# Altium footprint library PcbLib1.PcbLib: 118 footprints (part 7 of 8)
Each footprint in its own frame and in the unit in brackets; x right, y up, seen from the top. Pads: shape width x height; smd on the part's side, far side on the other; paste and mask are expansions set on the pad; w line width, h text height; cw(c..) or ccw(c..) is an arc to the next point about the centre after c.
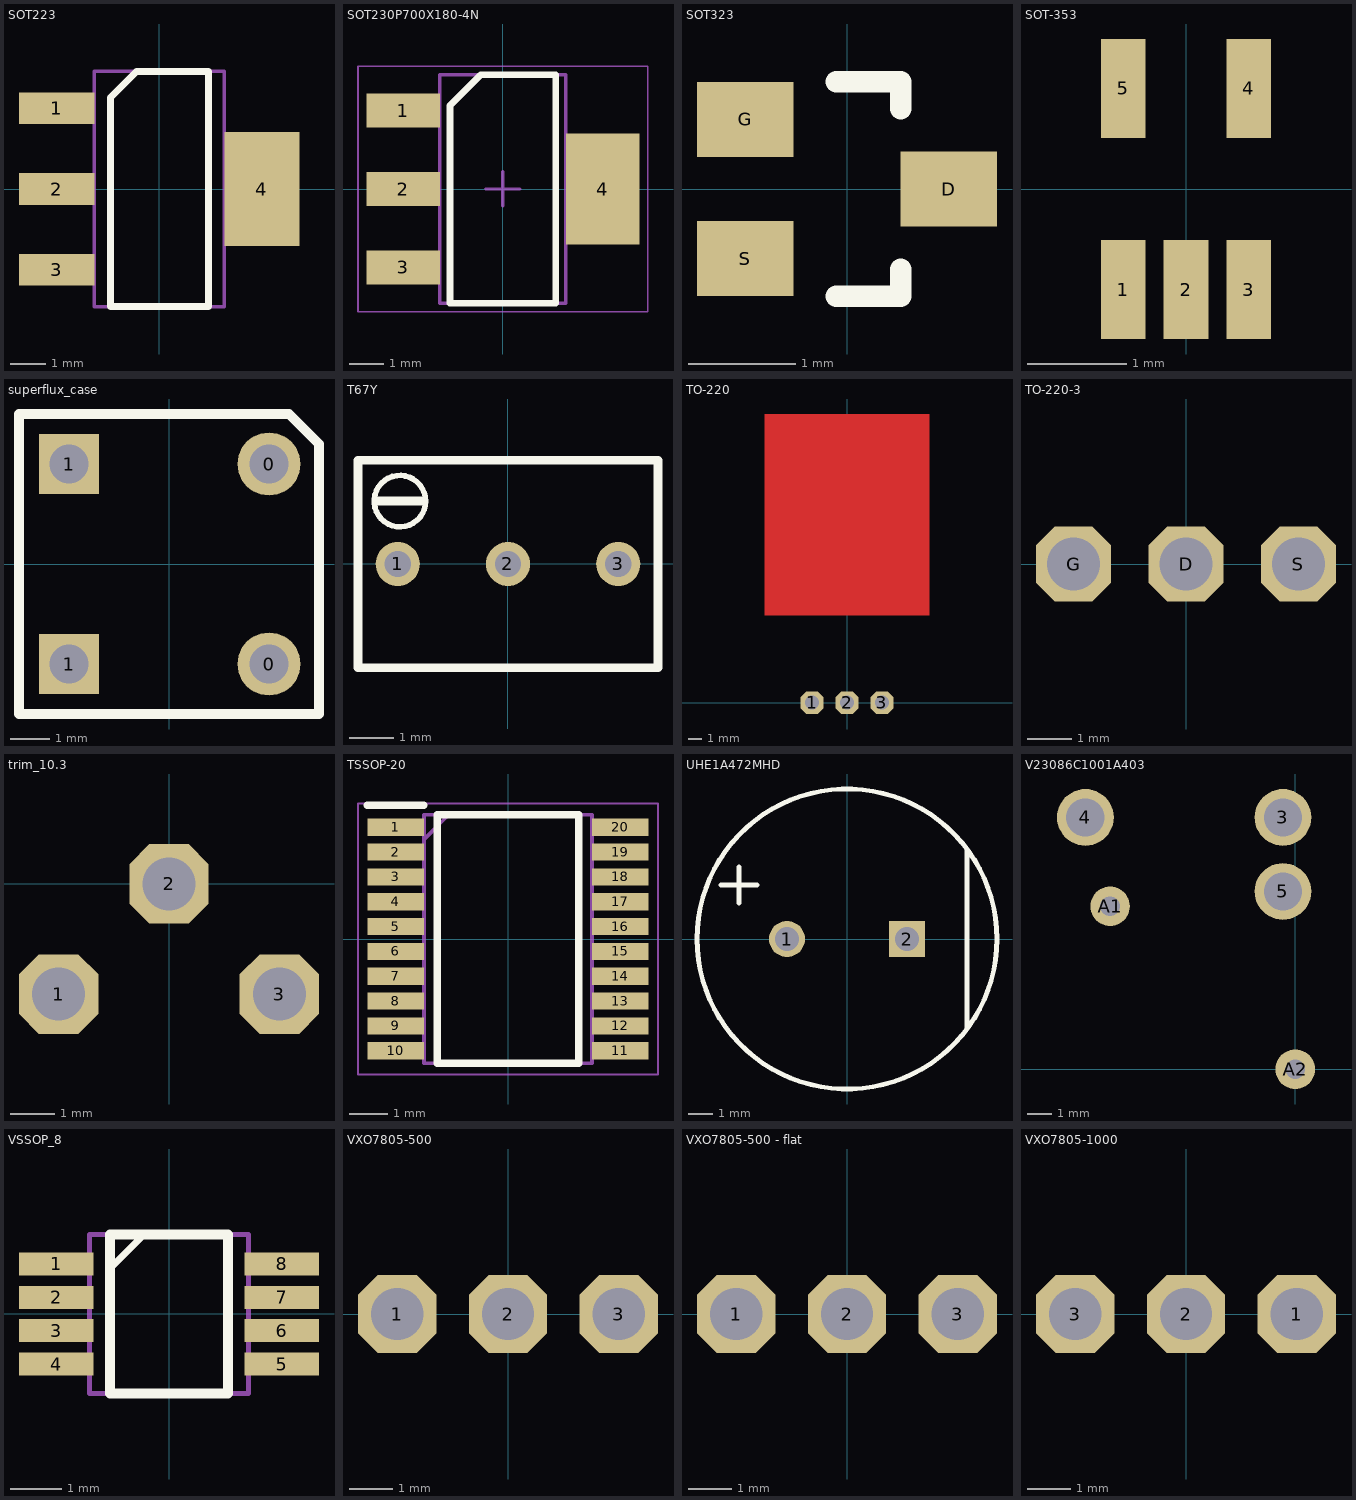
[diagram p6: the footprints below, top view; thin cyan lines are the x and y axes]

## SOT223 [mm]
height 1.8
pads (4):
  rect 2.15x0.9 smd: 1(-2.925,2.3) 2(-2.925,0) 3(-2.925,-2.3)
  rect 2.15x3.25 smd: 4(2.925,0)
Top Overlay:
  lines w0.2: -1.397,-3.35 1.397,-3.35 1.397,3.35 -0.65,3.35 -1.397,2.603 -1.397,-3.35
Mechanical 13:
  lines w0.1: -1.85,-3.35 1.85,-3.35 1.85,3.35 -1.85,3.35 -1.85,-3.35
3D body "SOT223.step": height 1.8, standoff 0, extent -3.5,-3.35 3.5,3.35

## SOT230P700X180-4N [mm] "SOT223, 4-Leads, Body 6,50x7,00mm (avg), Pitch 2,30mm, IPC Medium Density"
height 1.8
pads (4):
  rect 2.15x1 smd: 1(-2.925,2.3) 2(-2.925,0) 3(-2.925,-2.3)
  rect 2.15x3.25 smd: 4(2.925,0)
Top Overlay:
  lines w0.2: -1.55,-3.35 -1.55,2.45 -0.65,3.35 1.55,3.35 1.55,-3.35 -1.55,-3.35
Mechanical 13:
  lines w0.1: -1.85,-3.35 -1.85,3.35 1.85,3.35 1.85,-3.35 -1.85,-3.35
Mechanical 15:
  lines w0.05: -4.25,-3.6 -4.25,3.6 4.25,3.6 4.25,-3.6 -4.25,-3.6
  lines w0.1: -0.5,0 0.5,0 ; 0,-0.5 0,0.5
3D body "SOT-223.step": height 1.81, standoff 0, extent -3.645,-3.353 3.645,3.353

## SOT323 [mm] "SOT23, 3-Leads, Body 1,90x2,10mm, Pitch 0,65mm, IPC Medium Density"
height 1.1
pads (3):
  rect 0.9x0.7 smd: D(0.95,0) G(-0.95,0.65) S(-0.95,-0.65)
Top Overlay:
  lines w0.2: -0.1,-1 0.5,-1 0.5,-0.75 ; -0.1,1 0.5,1 0.5,0.75
3D body "SOT323.step": height 1.1, standoff 0, extent -1.1,-1 1.1,1

## SOT-353 [mm]
pads (5):
  rect 0.45x1 smd: 1(-0.635,-1.016) 2(0,-1.016) 3(0.635,-1.016) 4(0.635,1.016) 5(-0.635,1.016)
3D body "sot353.step": height 1, standoff 0, extent -1.05,-1.15 1.05,1.15

## superflux_case [mm]
pads (4):
  round 1.6 hole 1: 0(2.54,-2.54) 0(2.54,2.54)
  rect 1.524x1.524 hole 1: 1(-2.54,-2.54) 1(-2.54,2.54)
Top Overlay:
  lines w0.254: 2.99,3.81 -3.81,3.81 -3.81,-3.81 3.81,-3.81 3.81,3.048 3.048,3.81

## T67Y [mm] "SR Passives potentiometer"
pads (3):
  round 1 hole 0.6: 1(-2.5,0) 2(0,0) 3(2.5,0)
Top Overlay:
  circle w0.127: c-2.45,1.425 r0.583
  lines w0.2: -2.95,1.425 -1.95,1.425 ; -3.4,-2.35 3.4,-2.35 3.4,2.35 -3.4,2.35 -3.4,-2.35
3D body "T93YA.STEP": height 11.1, standoff -3, extent -4.85,-2.5 4.85,2.5

## TO-220 [mm]
pads (3):
  oct 1.65x1.65 hole 1: 1(-2.54,0) 2(0,0) 3(2.54,0)
Top Layer:
  region: -5.969,20.955 5.969,20.955 5.969,6.35 -5.969,6.35
3D body "TO-220_horizontal.step": height 4.55, standoff -7.08, extent -4.95,-0.247 4.95,19.966

## TO-220-3 [mm]
pads (3):
  oct 1.7x1.7 hole 1.2 mask+0.05: D(0,0) G(-2.54,0) S(2.54,0)
3D body "TO-220-3.STEP": height 19.76, standoff -2.2, extent -4.95,-2.1 4.95,2.4

## trim_10.3 [mm] "10.3x4.5mm body vertical"
pads (3):
  oct 1.8x1.8 hole 1.2: 1(-2.5,-2.5) 2(0,0) 3(2.5,-2.5)
3D body "User Library-PT10LH.step": height 12.1, standoff -3.5, extent -5.15,-2.76 5.15,2

## TSSOP-20 [mm]
pads (20):
  rect 1.475x0.45 smd: 1(-2.938,2.925) 2(-2.938,2.275) 3(-2.938,1.625) 4(-2.938,0.975) 5(-2.938,0.325) 6(-2.938,-0.325) 7(-2.938,-0.975) 8(-2.938,-1.625) 9(-2.938,-2.275) 10(-2.938,-2.925) 11(2.938,-2.925) 12(2.938,-2.275) 13(2.938,-1.625) 14(2.938,-0.975) 15(2.938,-0.325) 16(2.938,0.325) 17(2.938,0.975) 18(2.938,1.625) 19(2.938,2.275) 20(2.938,2.925)
Top Overlay:
  lines w0.2: -3.675,3.5 -2.2,3.5 ; -1.85,-3.25 1.85,-3.25 1.85,3.25 -1.85,3.25 -1.85,-3.25
Mechanical 15:
  lines w0.1: -2.2,2.6 -1.55,3.25 ; -2.2,-3.25 2.2,-3.25 2.2,3.25 -2.2,3.25 -2.2,-3.25
Mechanical 20:
  lines w0.05: -3.925,-3.55 3.925,-3.55 3.925,3.55 -3.925,3.55 -3.925,-3.55
3D body "TXB0108PWR.stp": height 1.2, standoff 0, extent -3.2,-3.25 3.2,3.25

## UHE1A472MHD [mm] "12.5x35.5 ALU ELKO"
pads (2):
  round 1.5 hole 1: 1(-2.5,0)
  rect 1.5x1.5 hole 1: 2(2.5,0)
Top Overlay:
  circle w0.2: c0,0 r6.25
  lines w0.2: -5.25,2.25 -3.75,2.25 ; -4.5,1.5 -4.5,3 ; 5,-3.75 5,3.75
3D body "12.5x35.5_radial.STEP": height 35.5, standoff -3, extent -6.25,-6.248 6.25,6.25

## V23086C1001A403 [mm]
pads (5):
  round 2.3 hole 1.55: 3(-0.5,10.2) 4(-8.5,10.2) 5(-0.5,7.2)
  round 1.6 hole 0.8: A1(-7.5,6.6) A2(0,0)
3D body "c-1393280-6-b1-3d.STEP": height 10, standoff -2.7, extent -10.191,-1.397 1.809,11.603

## VSSOP_8 [mm]
height 1.1
pads (8):
  rect 1.45x0.45 smd: 1(-2.2,0.975) 2(-2.2,0.325) 3(-2.2,-0.325) 4(-2.2,-0.975) 5(2.2,-0.975) 6(2.2,-0.325) 7(2.2,0.325) 8(2.2,0.975)
Top Overlay:
  lines w0.127: -1.15,0.889 -0.508,1.531
  lines w0.2: -1.15,-1.55 -1.15,1.55 1.15,1.55 1.15,-1.55 -1.15,-1.55
Mechanical 13:
  lines w0.1: -1.55,-1.55 -1.55,1.55 1.55,1.55 1.55,-1.55 -1.55,-1.55
3D body "VSSOP_8.step": height 1.1, standoff 0, extent -2.45,-1.55 2.45,1.55

## VXO7805-500 [mm]
pads (3):
  oct 1.8x1.8 hole 1.2: 1(-2.54,0) 2(0,0) 3(2.54,0)
3D body "CUI_VXO7805-500.step": height 11.25, standoff -3.85, extent -4.99,-0.589 5.01,6.786

## VXO7805-500 - flat [mm] "flattened edition"
pads (3):
  oct 1.8x1.8 hole 1.2: 1(-2.54,0) 2(0,0) 3(2.54,0)
3D body "VXO7805-500_flat.STEP": height 8.6, standoff -3, extent -4.99,-9.73 5.01,1.27

## VXO7805-1000 [mm]
pads (3):
  oct 1.8x1.8 hole 1.2: 1(2.54,0) 2(0,0) 3(-2.54,0)
3D body "CUI_VXO7805-1000.stp": height 6.52, standoff -3.04, extent -5.75,-1.27 5.75,16.23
